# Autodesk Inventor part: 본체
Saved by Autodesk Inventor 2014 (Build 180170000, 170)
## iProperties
Created: 2025-02
Part Number: 본체
Material: 알루미늄 6061
Document SubType Name: Modeling
Designer: dg
Density: 2.71 g/cm^3
Appearance: 알루미늄 - 평지
Mass: 509.146 g
Surface Area: 646.258 cm^2
Volume: 187.877 cm^3
Author: jhkim
Creation Date: 2025-01-06
Sending System: Autodesk Inventor 2025
Preprocessor: ST-DEVELOPER v20
Author: dg
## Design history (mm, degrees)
node "본체1"
node "솔리드1"
node "기준1"
